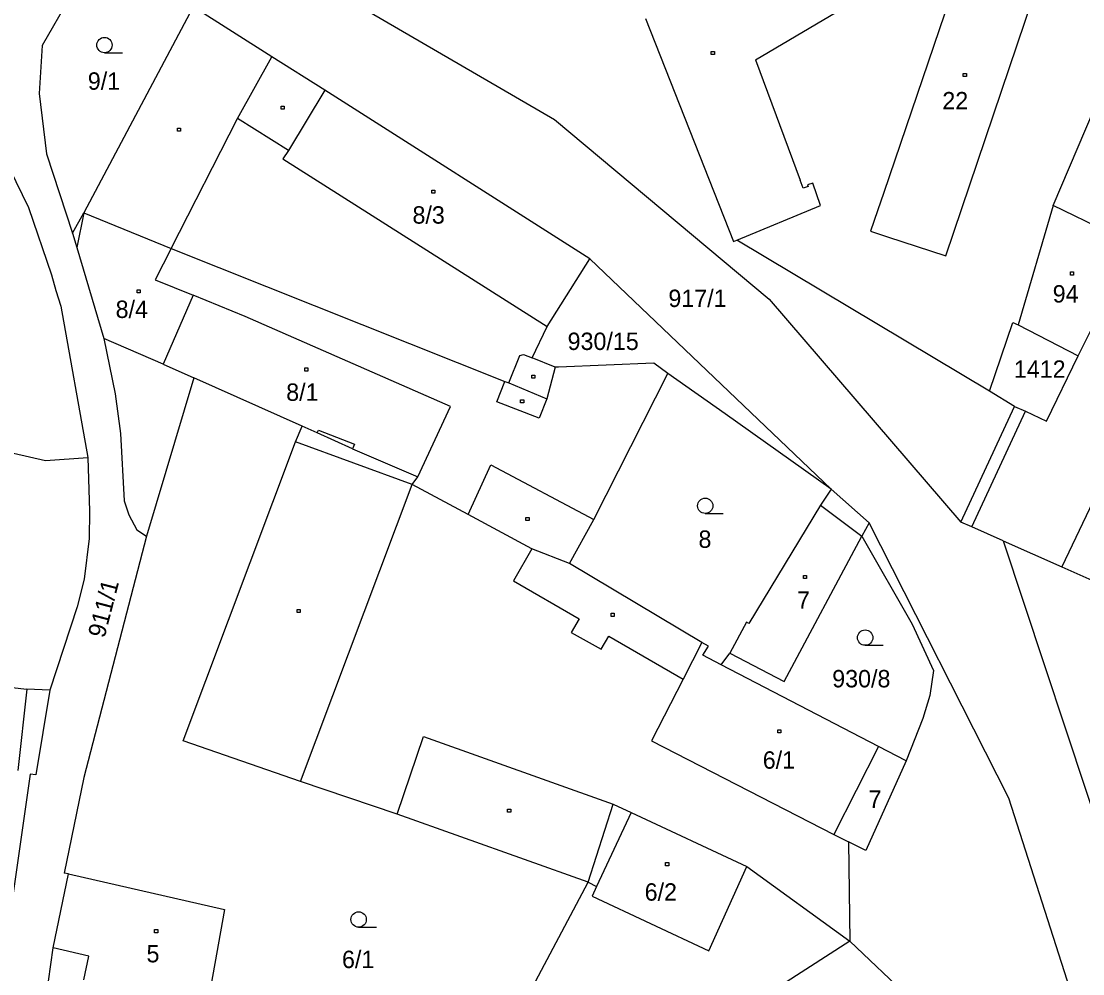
# Model space of a CAD drawing. Extents: x -796130 to -793145, y -1109506 to -1106267.
# Drawn here: x -794602 to -794498.3, y -1107769.6 to -1107676.5 of the extents above; entities that cross this region are included whole.
import ezdxf

# ---------------------------------------------------------------- set-up
doc = ezdxf.new("R2010")
doc.units = 0
for name, color, linetype in [('Vrstva 1', 7, 'Continuous'), ('Vrstva 14', 7, 'Continuous'), ('Vrstva 15', 7, 'Continuous'), ('Vrstva 2', 7, 'Continuous'), ('Vrstva 23', 7, 'Continuous'), ('Vrstva 25', 7, 'Continuous')]:
    doc.layers.add(name, color=color, linetype=linetype)

msp = doc.modelspace()

# ---------------------------------------------------------------- linework, layer by layer
at = {"layer": 'Vrstva 1'}
for p, q in [((-794581.21, -1107667.86), (-794549.92, -1107686.13)), ((-794595.21, -1107670.52), (-794600.01, -1107678.9)), ((-794577.55, -1107680), (-794585.23, -1107675.12)), ((-794585.56, -1107675.74), (-794595.94, -1107695.24)), ((-794541.04, -1107676.25), (-794532.44, -1107698.06)), ((-794600.01, -1107678.9), (-794600.28, -1107683.6)), ((-794572.39, -1107683.27), (-794577.55, -1107680)), ((-794600.28, -1107683.6), (-794599.59, -1107689.49)), ((-794546.47, -1107699.74), (-794572.39, -1107683.27)), ((-794501.21, -1107694.54), (-794496.41, -1107683.31)), ((-794549.92, -1107686.13), (-794528.94, -1107703.68)), ((-794599.59, -1107689.49), (-794597.02, -1107697.25)), ((-794603.18, -1107690.93), (-794601.34, -1107694.72)), ((-794601.34, -1107694.72), (-794599.08, -1107701.32)), ((-794597.02, -1107697.25), (-794595.94, -1107695.24)), ((-794595.94, -1107695.24), (-794587.4, -1107698.75)), ((-794501.21, -1107694.54), (-794504.61, -1107706.21)), ((-794493.34, -1107698.36), (-794501.21, -1107694.54)), ((-794597.02, -1107697.25), (-794596.6, -1107698.63)), ((-794532.44, -1107698.06), (-794532.12, -1107697.93)), ((-794507.41, -1107712.68), (-794532.12, -1107697.93)), ((-794498.75, -1107709.22), (-794493.34, -1107698.36)), ((-794596.6, -1107698.63), (-794593.97, -1107707.53)), ((-794587.4, -1107698.75), (-794588.95, -1107701.8)), ((-794587.4, -1107698.75), (-794554.8, -1107711.74)), ((-794550.65, -1107706.38), (-794546.47, -1107699.74)), ((-794522.89, -1107722.25), (-794546.47, -1107699.74)), ((-794599.08, -1107701.32), (-794598.66, -1107702.83)), ((-794588.95, -1107701.8), (-794585.24, -1107703.31)), ((-794598.66, -1107702.83), (-794598.16, -1107704.38)), ((-794585.24, -1107703.31), (-794588.18, -1107710.06)), ((-794598.16, -1107704.38), (-794595.54, -1107719.16)), ((-794528.94, -1107703.68), (-794510.21, -1107725.48)), ((-794552.12, -1107709.44), (-794550.65, -1107706.38)), ((-794507.41, -1107712.68), (-794505.14, -1107705.96)), ((-794505.14, -1107705.96), (-794504.61, -1107706.21)), ((-794504.61, -1107706.21), (-794498.75, -1107709.22)), ((-794593.97, -1107707.53), (-794592.85, -1107712.94)), ((-794554.39, -1107711.87), (-794553.31, -1107709.21)), ((-794553.31, -1107709.21), (-794552.96, -1107709.1)), ((-794552.96, -1107709.1), (-794552.12, -1107709.44)), ((-794549.85, -1107710.34), (-794552.12, -1107709.44)), ((-794501.85, -1107715.63), (-794498.75, -1107709.22)), ((-794588.18, -1107710.06), (-794585.17, -1107711.37)), ((-794549.55, -1107710.33), (-794549.85, -1107710.34)), ((-794540.23, -1107709.95), (-794549.55, -1107710.33)), ((-794538.87, -1107710.95), (-794540.23, -1107709.95)), ((-794585.17, -1107711.37), (-794589.8, -1107726.86)), ((-794574.59, -1107716.1), (-794585.17, -1107711.37)), ((-794554.8, -1107711.74), (-794554.39, -1107711.87)), ((-794546.1, -1107725.24), (-794538.87, -1107710.95)), ((-794533.24, -1107714.9), (-794538.87, -1107710.95)), ((-794504.98, -1107714.18), (-794507.41, -1107712.68)), ((-794592.85, -1107712.94), (-794592.34, -1107716.81)), ((-794522.89, -1107722.25), (-794533.24, -1107714.9)), ((-794510.21, -1107725.48), (-794504.98, -1107714.18)), ((-794504.98, -1107714.18), (-794503.9, -1107714.64)), ((-794503.9, -1107714.64), (-794501.85, -1107715.63)), ((-794612.84, -1107716.43), (-794599.68, -1107719.46)), ((-794592.34, -1107716.81), (-794591.99, -1107723.39)), ((-794575.24, -1107717.63), (-794574.59, -1107716.1)), ((-794573.13, -1107716.76), (-794574.59, -1107716.1)), ((-794569.66, -1107718.31), (-794573.13, -1107716.76)), ((-794586.22, -1107746.87), (-794575.24, -1107717.63)), ((-794569.66, -1107718.31), (-794563.3, -1107721.07)), ((-794599.68, -1107719.46), (-794595.54, -1107719.16)), ((-794595.54, -1107719.16), (-794595.36, -1107724.42)), ((-794563.83, -1107721.82), (-794563.3, -1107721.07)), ((-794558.38, -1107724.75), (-794563.83, -1107721.82)), ((-794522.89, -1107722.25), (-794523.94, -1107723.82)), ((-794519.19, -1107725.54), (-794522.89, -1107722.25)), ((-794591.99, -1107723.39), (-794591.53, -1107724.79)), ((-794523.94, -1107723.82), (-794530.95, -1107735.4)), ((-794595.36, -1107724.42), (-794595.41, -1107727.1)), ((-794591.53, -1107724.79), (-794590.74, -1107726.25)), ((-794552.16, -1107728.11), (-794558.38, -1107724.75)), ((-794548.47, -1107729.53), (-794546.1, -1107725.24)), ((-794590.74, -1107726.25), (-794589.8, -1107726.86)), ((-794519.19, -1107725.54), (-794519.88, -1107726.86)), ((-794505.52, -1107752.46), (-794519.19, -1107725.54)), ((-794509.15, -1107725.95), (-794510.21, -1107725.48)), ((-794506.09, -1107727.3), (-794509.15, -1107725.95)), ((-794589.8, -1107726.86), (-794595.93, -1107750.46)), ((-794595.41, -1107727.1), (-794595.9, -1107731.07)), ((-794527.49, -1107741.05), (-794519.88, -1107726.86)), ((-794519.88, -1107726.86), (-794514.97, -1107735.45)), ((-794506.09, -1107727.3), (-794500.34, -1107729.85)), ((-794506.09, -1107727.3), (-794483.18, -1107796.53)), ((-794548.47, -1107729.53), (-794552.16, -1107728.11)), ((-794535.52, -1107737.24), (-794548.47, -1107729.53)), ((-794500.34, -1107729.85), (-794495.7, -1107731.95)), ((-794595.9, -1107731.07), (-794596.57, -1107733.78)), ((-794596.57, -1107733.78), (-794599.24, -1107741.92)), ((-794531.16, -1107735.27), (-794532.81, -1107738.31)), ((-794530.95, -1107735.4), (-794531.16, -1107735.27)), ((-794514.97, -1107735.45), (-794512.88, -1107740)), ((-794534.89, -1107737.61), (-794535.52, -1107737.24)), ((-794535.44, -1107738.5), (-794534.89, -1107737.61)), ((-794533.65, -1107739.43), (-794535.44, -1107738.5)), ((-794533.65, -1107739.43), (-794532.81, -1107738.31)), ((-794532.81, -1107738.31), (-794527.49, -1107741.05)), ((-794619.11, -1107739.81), (-794601.49, -1107741.83)), ((-794518.28, -1107747.43), (-794533.65, -1107739.43)), ((-794512.88, -1107740), (-794513.24, -1107742.45)), ((-794599.24, -1107741.92), (-794601.49, -1107741.83)), ((-794599.24, -1107741.92), (-794600.62, -1107750.18)), ((-794513.24, -1107742.45), (-794513.92, -1107744.67)), ((-794513.92, -1107744.67), (-794515.57, -1107748.81)), ((-794574.74, -1107750.85), (-794586.22, -1107746.87)), ((-794518.28, -1107747.43), (-794522.63, -1107756.02)), ((-794515.57, -1107748.81), (-794518.28, -1107747.43)), ((-794515.57, -1107748.81), (-794519.52, -1107757.6)), ((-794601.16, -1107750.12), (-794603.21, -1107764.49)), ((-794600.62, -1107750.18), (-794601.16, -1107750.12)), ((-794595.93, -1107750.46), (-794597.85, -1107759.8)), ((-794565.31, -1107754.05), (-794574.74, -1107750.85)), ((-794546.65, -1107760.67), (-794544.21, -1107753.07)), ((-794544.21, -1107753.07), (-794542.44, -1107753.86)), ((-794488.44, -1107805.91), (-794505.52, -1107752.46)), ((-794546.65, -1107760.67), (-794565.31, -1107754.05)), ((-794542.44, -1107753.86), (-794531.12, -1107759.14)), ((-794522.63, -1107756.02), (-794521.21, -1107756.74)), ((-794521.21, -1107756.74), (-794521.06, -1107766.45)), ((-794519.52, -1107757.6), (-794521.21, -1107756.74)), ((-794534.86, -1107767.41), (-794531.12, -1107759.14)), ((-794531.12, -1107759.14), (-794521.06, -1107766.45)), ((-794598.91, -1107767.1), (-794597.43, -1107759.88)), ((-794597.43, -1107759.88), (-794597.85, -1107759.8)), ((-794597.43, -1107759.88), (-794582.18, -1107763.36)), ((-794563.76, -1107793.02), (-794546.65, -1107760.67)), ((-794546.65, -1107760.67), (-794545.82, -1107761.1)), ((-794545.82, -1107761.1), (-794546.26, -1107762.06)), ((-794546.26, -1107762.06), (-794534.86, -1107767.41)), ((-794582.18, -1107763.36), (-794583.53, -1107770.83)), ((-794521.06, -1107766.45), (-794532.19, -1107773.6)), ((-794521.06, -1107766.45), (-794514.36, -1107772.81)), ((-794600.41, -1107777.68), (-794598.91, -1107767.1))]:
    msp.add_line(p, q, dxfattribs=at)
at = {"layer": 'Vrstva 2'}
for p, q in [((-794508.96, -1107667.39), (-794517.75, -1107693.26)), ((-794511.68, -1107699.45), (-794501.74, -1107670.05)), ((-794530.29, -1107680.31), (-794521.06, -1107674.84)), ((-794580.91, -1107686.02), (-794577.55, -1107680)), ((-794530.29, -1107680.31), (-794525.92, -1107692.06)), ((-794572.39, -1107683.27), (-794575.92, -1107689.17)), ((-794587.4, -1107698.75), (-794580.91, -1107686.02)), ((-794575.92, -1107689.17), (-794580.91, -1107686.02)), ((-794575.92, -1107689.17), (-794576.48, -1107689.98)), ((-794576.48, -1107689.98), (-794550.65, -1107706.38)), ((-794525.63, -1107692.84), (-794525.92, -1107692.06)), ((-794525.14, -1107692.67), (-794525.63, -1107692.84)), ((-794524.68, -1107692.36), (-794525.19, -1107692.53)), ((-794525.19, -1107692.53), (-794525.14, -1107692.67)), ((-794523.94, -1107694.55), (-794524.68, -1107692.36)), ((-794517.75, -1107693.26), (-794518.36, -1107695.07)), ((-794595.94, -1107695.24), (-794596.6, -1107698.63)), ((-794532.12, -1107697.93), (-794523.94, -1107694.55)), ((-794518.36, -1107695.07), (-794519.04, -1107697.06)), ((-794519.04, -1107697.06), (-794517.38, -1107697.6)), ((-794517.38, -1107697.6), (-794511.68, -1107699.45)), ((-794486.91, -1107701.49), (-794500.34, -1107729.85)), ((-794580.15, -1107705.39), (-794585.24, -1107703.31)), ((-794560.08, -1107714.18), (-794580.15, -1107705.39)), ((-794588.18, -1107710.06), (-794593.97, -1107707.53)), ((-794549.85, -1107710.34), (-794550.69, -1107713.45)), ((-794555.58, -1107713.72), (-794554.8, -1107711.74)), ((-794554.39, -1107711.87), (-794550.69, -1107713.45)), ((-794551.43, -1107715.34), (-794555.58, -1107713.72)), ((-794550.69, -1107713.45), (-794551.43, -1107715.34)), ((-794563.3, -1107721.07), (-794560.08, -1107714.18)), ((-794509.15, -1107725.95), (-794503.9, -1107714.64)), ((-794573.13, -1107716.76), (-794573.01, -1107716.49)), ((-794573.01, -1107716.49), (-794569.46, -1107717.87)), ((-794563.83, -1107721.82), (-794575.24, -1107717.63)), ((-794569.46, -1107717.87), (-794569.66, -1107718.31)), ((-794558.38, -1107724.75), (-794556.14, -1107719.88)), ((-794556.14, -1107719.88), (-794546.1, -1107725.24)), ((-794574.74, -1107750.85), (-794563.83, -1107721.82)), ((-794523.94, -1107723.82), (-794519.88, -1107726.86)), ((-794552.16, -1107728.11), (-794553.95, -1107731.23)), ((-794553.95, -1107731.23), (-794547.53, -1107734.95)), ((-794547.53, -1107734.95), (-794548.3, -1107736.29)), ((-794548.3, -1107736.29), (-794545.38, -1107737.92)), ((-794545.38, -1107737.92), (-794544.63, -1107736.62)), ((-794544.63, -1107736.62), (-794537.36, -1107740.83)), ((-794535.52, -1107737.24), (-794537.36, -1107740.83)), ((-794537.36, -1107740.83), (-794540.46, -1107746.88)), ((-794601.49, -1107741.83), (-794602.38, -1107749.75)), ((-794565.31, -1107754.05), (-794562.74, -1107746.44)), ((-794562.74, -1107746.44), (-794544.21, -1107753.07)), ((-794540.46, -1107746.88), (-794522.63, -1107756.02)), ((-794542.44, -1107753.86), (-794545.82, -1107761.1)), ((-794595.43, -1107767.9), (-794598.91, -1107767.1)), ((-794595.94, -1107770.22), (-794595.43, -1107767.9))]:
    msp.add_line(p, q, dxfattribs=at)
at = {"layer": 'Vrstva 23'}
for p, q in [((-794593.91, -1107679.6), (-794592.16, -1107679.6)), ((-794535.2, -1107724.64), (-794533.45, -1107724.64)), ((-794519.57, -1107737.53), (-794517.82, -1107737.53)), ((-794569.07, -1107765.08), (-794567.32, -1107765.08))]:
    msp.add_line(p, q, dxfattribs=at)
for centre in [(-794593.91, -1107678.85), (-794535.2, -1107723.89), (-794519.57, -1107736.78), (-794569.07, -1107764.33)]:
    msp.add_circle(centre, 0.75, dxfattribs=at)
at = {"layer": 'Vrstva 25'}
for p, q in [((-794534.61, -1107679.49), (-794534.31, -1107679.49)), ((-794534.61, -1107679.79), (-794534.61, -1107679.49)), ((-794534.31, -1107679.49), (-794534.31, -1107679.79)), ((-794534.31, -1107679.79), (-794534.61, -1107679.79)), ((-794509.98, -1107681.64), (-794509.68, -1107681.64)), ((-794509.98, -1107681.94), (-794509.98, -1107681.64)), ((-794509.68, -1107681.64), (-794509.68, -1107681.94)), ((-794509.68, -1107681.94), (-794509.98, -1107681.94)), ((-794576.64, -1107684.82), (-794576.34, -1107684.82)), ((-794576.64, -1107685.12), (-794576.64, -1107684.82)), ((-794576.34, -1107684.82), (-794576.34, -1107685.12)), ((-794576.34, -1107685.12), (-794576.64, -1107685.12)), ((-794586.77, -1107686.97), (-794586.47, -1107686.97)), ((-794586.77, -1107687.27), (-794586.77, -1107686.97)), ((-794586.47, -1107687.27), (-794586.77, -1107687.27)), ((-794586.47, -1107686.97), (-794586.47, -1107687.27)), ((-794561.92, -1107693.03), (-794561.62, -1107693.03)), ((-794561.92, -1107693.33), (-794561.92, -1107693.03)), ((-794561.62, -1107693.03), (-794561.62, -1107693.33)), ((-794561.62, -1107693.33), (-794561.92, -1107693.33)), ((-794499.5, -1107701.03), (-794499.2, -1107701.03)), ((-794499.5, -1107701.33), (-794499.5, -1107701.03)), ((-794499.2, -1107701.33), (-794499.5, -1107701.33)), ((-794499.2, -1107701.03), (-794499.2, -1107701.33)), ((-794590.73, -1107702.77), (-794590.43, -1107702.77)), ((-794590.73, -1107703.07), (-794590.73, -1107702.77)), ((-794590.43, -1107703.07), (-794590.73, -1107703.07)), ((-794590.43, -1107702.77), (-794590.43, -1107703.07)), ((-794574.33, -1107710.42), (-794574.03, -1107710.42)), ((-794574.33, -1107710.72), (-794574.33, -1107710.42)), ((-794574.03, -1107710.72), (-794574.33, -1107710.72)), ((-794574.03, -1107710.42), (-794574.03, -1107710.72)), ((-794552.16, -1107711.11), (-794551.86, -1107711.11)), ((-794552.16, -1107711.41), (-794552.16, -1107711.11)), ((-794551.86, -1107711.41), (-794552.16, -1107711.41)), ((-794551.86, -1107711.11), (-794551.86, -1107711.41)), ((-794553.24, -1107713.52), (-794552.94, -1107713.52)), ((-794553.24, -1107713.82), (-794553.24, -1107713.52)), ((-794552.94, -1107713.82), (-794553.24, -1107713.82)), ((-794552.94, -1107713.52), (-794552.94, -1107713.82)), ((-794552.72, -1107725.02), (-794552.42, -1107725.02)), ((-794552.72, -1107725.32), (-794552.72, -1107725.02)), ((-794552.42, -1107725.32), (-794552.72, -1107725.32)), ((-794552.42, -1107725.02), (-794552.42, -1107725.32)), ((-794525.59, -1107730.7), (-794525.29, -1107730.7)), ((-794525.59, -1107731), (-794525.59, -1107730.7)), ((-794525.29, -1107731), (-794525.59, -1107731)), ((-794525.29, -1107730.7), (-794525.29, -1107731)), ((-794575.07, -1107734.03), (-794574.77, -1107734.03)), ((-794575.07, -1107734.33), (-794575.07, -1107734.03)), ((-794574.77, -1107734.33), (-794575.07, -1107734.33)), ((-794574.77, -1107734.03), (-794574.77, -1107734.33)), ((-794544.4, -1107734.4), (-794544.1, -1107734.4)), ((-794544.4, -1107734.7), (-794544.4, -1107734.4)), ((-794544.1, -1107734.4), (-794544.1, -1107734.7)), ((-794544.1, -1107734.7), (-794544.4, -1107734.7)), ((-794528.12, -1107745.79), (-794527.82, -1107745.79)), ((-794528.12, -1107746.09), (-794528.12, -1107745.79)), ((-794527.82, -1107746.09), (-794528.12, -1107746.09)), ((-794527.82, -1107745.79), (-794527.82, -1107746.09)), ((-794554.51, -1107753.54), (-794554.21, -1107753.54)), ((-794554.51, -1107753.84), (-794554.51, -1107753.54)), ((-794554.21, -1107753.84), (-794554.51, -1107753.84)), ((-794554.21, -1107753.54), (-794554.21, -1107753.84)), ((-794539.07, -1107758.77), (-794538.77, -1107758.77)), ((-794539.07, -1107759.07), (-794539.07, -1107758.77)), ((-794538.77, -1107759.07), (-794539.07, -1107759.07)), ((-794538.77, -1107758.77), (-794538.77, -1107759.07)), ((-794589.01, -1107765.32), (-794588.71, -1107765.32)), ((-794589.01, -1107765.62), (-794589.01, -1107765.32)), ((-794588.71, -1107765.62), (-794589.01, -1107765.62)), ((-794588.71, -1107765.32), (-794588.71, -1107765.62))]:
    msp.add_line(p, q, dxfattribs=at)

# ---------------------------------------------------------------- texts
at = {"layer": 'Vrstva 14'}
for s, p in [('9/1', (-794595.54, -1107683.22)), ('917/1', (-794538.8, -1107704.46)), ('930/15', (-794548.65, -1107708.66)), ('1412', (-794505.04, -1107711.38)), ('8', (-794535.86, -1107728)), ('930/8', (-794522.79, -1107741.64)), ('7', (-794519.24, -1107753.42)), ('6/1', (-794570.7, -1107769.08))]:
    msp.add_text(s, height=1.7, dxfattribs=at).set_placement(p)
msp.add_text('911/1', height=1.7, rotation=75.41109, dxfattribs=at).set_placement((-794593.91, -1107736.89))
at = {"layer": 'Vrstva 15'}
for s, p in [('22', (-794512.03, -1107685.14)), ('8/3', (-794563.81, -1107696.31)), ('94', (-794501.243, -1107704.02)), ('8/4', (-794592.82, -1107705.53)), ('8/1', (-794576.15, -1107713.63)), ('7', (-794526.23, -1107733.95)), ('6/1', (-794529.58, -1107749.59)), ('6/2', (-794541.12, -1107762.49)), ('5', (-794589.8, -1107768.52))]:
    msp.add_text(s, height=1.7, dxfattribs=at).set_placement(p)

doc.saveas('drawing.dxf')
